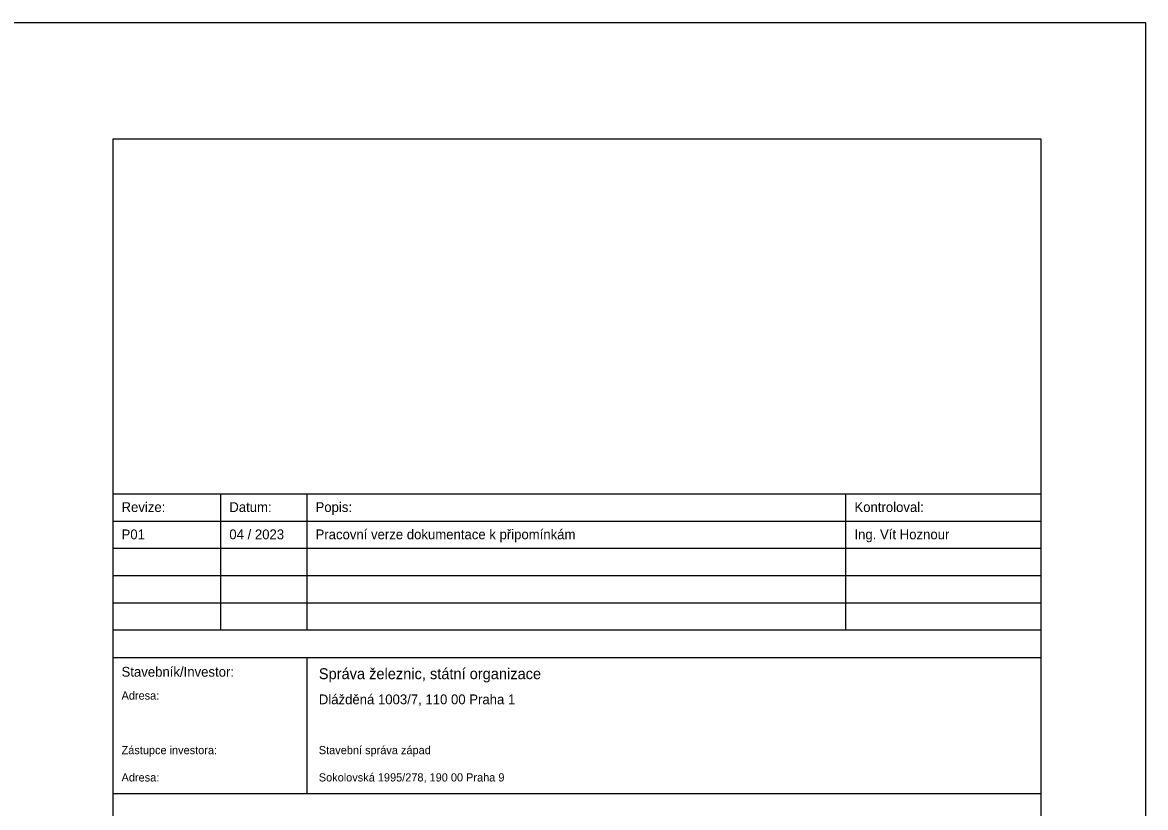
# Model space of a CAD drawing. Extents: x -757891 to -747391, y -1166581 to -1159156.
# Drawn here: x -752536 to -747391, y -1162753 to -1159156 of the extents above; entities that cross this region are included whole.
import ezdxf

# ---------------------------------------------------------------- set-up
doc = ezdxf.new("R2010")
doc.units = 0
doc.layers.add('formát', color=7, linetype='Continuous')
doc.layers.add('SO 11-10-01_popisove_pole', color=7, linetype='Continuous')

msp = doc.modelspace()

# ---------------------------------------------------------------- linework, layer by layer
at = {"layer": 'formát'}
msp.add_lwpolyline([(-752641.5, -1159156.4), (-747391.5, -1159156.4), (-747391.5, -1166581.4), (-752641.5, -1166581.4)], close=True, dxfattribs=at)
at = {"layer": 'SO 11-10-01_popisove_pole'}
for p, q in [((-751627.4, -1161940.2), (-751627.4, -1161315.2)), ((-751232.4, -1161940.2), (-751232.4, -1161315.2)), ((-748763.7, -1161940.2), (-748763.7, -1161315.2)), ((-752121.2, -1161440.2), (-747871.2, -1161440.2)), ((-752121.2, -1161565.2), (-747871.2, -1161565.2)), ((-752121.2, -1161690.2), (-747871.2, -1161690.2)), ((-752121.2, -1161815.2), (-747871.2, -1161815.2)), ((-751232.4, -1162690.2), (-751232.4, -1162065.2))]:
    msp.add_line(p, q, dxfattribs=at)
for points in [[(-752121.2, -1159690.2), (-747871.2, -1159690.2), (-747871.2, -1166190.2), (-752121.2, -1166190.2)], [(-752121.2, -1161315.2), (-747871.2, -1161315.2), (-747871.2, -1161940.2), (-752121.2, -1161940.2)], [(-752121.2, -1162065.2), (-747871.2, -1162065.2), (-747871.2, -1162690.2), (-752121.2, -1162690.2)]]:
    msp.add_lwpolyline(points, close=True, dxfattribs=at)

# ---------------------------------------------------------------- texts
for s, height, p in [('Revize:', 45, (-752082.5, -1161398.9)), ('Datum:', 45, (-751588.8, -1161398.9)), ('Popis:', 45, (-751193.8, -1161398.9)), ('Kontroloval:', 45, (-748725, -1161398.9)), ('P01', 45, (-752082.5, -1161523.9)), ('04 / 2023', 45, (-751588.8, -1161523.9)), ('Pracovní verze dokumentace k připomínkám', 45, (-751193.8, -1161523.9)), ('Ing. Vít Hoznour', 45, (-748725, -1161523.9)), ('Stavebník/Investor:', 45, (-752082.5, -1162153.4)), ('Správa železnic, státní organizace', 50, (-751178.8, -1162164.7)), ('Adresa:', 37.5, (-752082.5, -1162258.4)), ('Dlážděná 1003/7, 110 00 Praha 1', 45, (-751178.8, -1162279.7)), ('Zástupce investora:', 37.5, (-752082.5, -1162508.4)), ('Stavební správa západ', 37.5, (-751178.8, -1162508.4)), ('Adresa:', 37.5, (-752082.5, -1162633.4)), ('Sokolovská 1995/278, 190 00 Praha 9', 37.5, (-751178.8, -1162633.4))]:
    msp.add_text(s, height=height, rotation=360, dxfattribs=at).set_placement(p)

doc.saveas('drawing.dxf')
